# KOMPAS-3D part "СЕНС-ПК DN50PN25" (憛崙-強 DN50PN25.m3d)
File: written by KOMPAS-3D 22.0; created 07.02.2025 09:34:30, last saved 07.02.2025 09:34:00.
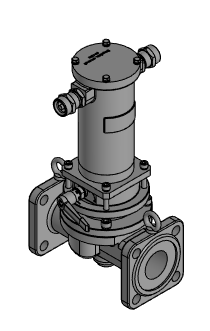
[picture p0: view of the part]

Document properties: Автор: setup; Полное имя файла: \\10.10.77.77\!! users\Савин А.Г\!Клапаны 3D для заказчика\СЕНС-ПК\1. СЕНС-ПК\СЕНС-ПК DN50PN25.m3d

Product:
- Body: Тело 3
    Масса: 17.833746
- Part/product: СЕНС-ПК DN50PN25
    Масса: 17.612808

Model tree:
1. Операция без истории:1

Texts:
  Body Specification ( left align )
  Body Specificaton ( centered )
